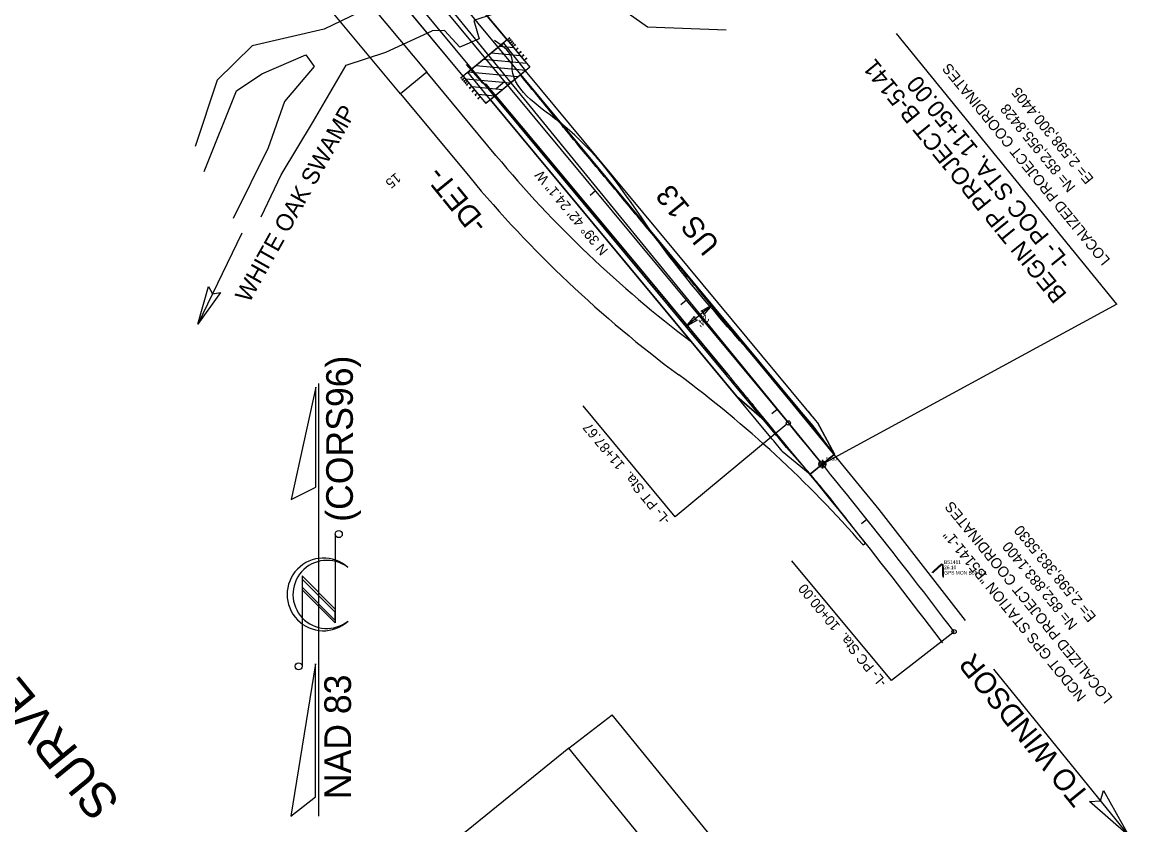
# Model space of a CAD drawing. Extents: x 2596159 to 2598075, y 851667 to 853493.
# Drawn here: x 2596820 to 2597521, y 852070 to 852579 of the extents above; entities that cross this region are included whole.
import ezdxf

# ---------------------------------------------------------------- set-up
doc = ezdxf.new("R2010")
doc.units = 0
for name, color, linetype in [('Cogo Default Point CELL', 7, 'Continuous'), ('CTL Sheet Text', 7, 'Continuous'), ('CTL Supplemental Horizontal and Vertical Cogo Comment', 7, 'Continuous'), ('CTL Supplemental Horizontal and Vertical Cogo Elevation', 7, 'Continuous'), ('CTL Supplemental Horizontal and Vertical Cogo Number', 7, 'Continuous'), ('Default', 7, 'Continuous'), ('Default Symbol CELL', 7, 'Continuous'), ('Default Symbol Cogo Number', 7, 'Continuous'), ('Exist Hydro Jurisdictional Stream or Body of Water', 7, 'Continuous'), ('Exist Roads EOP', 7, 'Continuous'), ('Old_Level_1', 7, 'Continuous'), ('Old_Level_2', 7, 'Continuous'), ('Old_Level_44', 7, 'Continuous'), ('Prop Dimension', 7, 'Continuous'), ('Prop Dimension Text', 7, 'Continuous'), ('Prop Horizontal Alignment', 7, 'Continuous'), ('Prop Horizontal Alignment Direction Label', 7, 'Continuous'), ('Prop Horizontal Alignment Station Label', 7, 'Continuous'), ('Prop Horizontal Alignment Tick Label', 7, 'Continuous'), ('Prop Horizontal Alignment Tick Large', 7, 'Continuous'), ('Prop Horizontal Alignment Tick Small', 7, 'Continuous'), ('Prop Shade Heavy', 7, 'Continuous'), ('Prop Shade Light', 7, 'Continuous'), ('Prop Shade Medium', 7, 'Continuous'), ('Prop Terminator CELL', 7, 'Continuous'), ('Sheet North Arrow CELL', 7, 'Continuous')]:
    doc.layers.add(name, color=color, linetype=linetype)

# ---------------------------------------------------------------- blocks, each defined once
blk = doc.blocks.new('DEFAULT SYMBOL')
at = {"layer": 'Default Symbol CELL'}
blk.add_lwpolyline([(0, 0.06), (0, -0.06), (0, 0), (0.06, 0), (-0.06, 0)], dxfattribs=at)
blk.add_circle((0, 0), 0.0469, dxfattribs=at)

msp = doc.modelspace()

# ---------------------------------------------------------------- linework, layer by layer
at = {"layer": 'Cogo Default Point CELL'}
msp.add_line((2597326.72, 852298.64), (2596871.93, 852856.6), dxfattribs=at)
at = {"layer": 'Default'}
for p, q in [((2597313.49, 852331.71), (2596966.4, 852749.69)), ((2597313.49, 852331.71), (2596966.4, 852749.69)), ((2597296.87, 852317.91), (2596949.78, 852735.9)), ((2597296.87, 852317.91), (2596949.78, 852735.9)), ((2597127.02, 852567.54), (2597075.27, 852629.86)), ((2597127.02, 852567.54), (2597075.27, 852629.86)), ((2597099.3, 852544.57), (2597047.55, 852606.88)), ((2597099.3, 852544.57), (2597047.55, 852606.88)), ((2597127.02, 852567.54), (2597099.3, 852544.57)), ((2597127.02, 852567.54), (2597099.3, 852544.57)), ((2597127.22, 852567.3), (2597126.77, 852567.34)), ((2597127.22, 852567.3), (2597126.77, 852567.34)), ((2597127.02, 852567.54), (2597128.4, 852568.69)), ((2597127.02, 852567.54), (2597137.79, 852554.55)), ((2597127.02, 852567.54), (2597141.38, 852550.22)), ((2597127.02, 852567.54), (2597141.38, 852550.22)), ((2597127.91, 852566.46), (2597129.3, 852567.61)), ((2597128.07, 852569.09), (2597128.73, 852568.29)), ((2597128.81, 852565.38), (2597130.2, 852566.53)), ((2597128.97, 852568.01), (2597129.63, 852567.21)), ((2597129.71, 852564.3), (2597131.09, 852565.44)), ((2597129.87, 852566.92), (2597130.53, 852566.13)), ((2597130.61, 852563.21), (2597131.99, 852564.36)), ((2597130.77, 852565.84), (2597131.42, 852565.05)), ((2597131.66, 852564.76), (2597132.32, 852563.96)), ((2597135.33, 852557.51), (2597116.97, 852559.21)), ((2597135.33, 852557.51), (2597116.97, 852559.21)), ((2597131.27, 852562.41), (2597121.87, 852563.28)), ((2597131.27, 852562.41), (2597121.87, 852563.28)), ((2597132.4, 852561.05), (2597133.79, 852562.2)), ((2597133.46, 852562.59), (2597134.12, 852561.8)), ((2597134.2, 852558.88), (2597135.58, 852560.03)), ((2597135.25, 852560.43), (2597135.91, 852559.63)), ((2597135.99, 852556.72), (2597137.38, 852557.87)), ((2597137.05, 852558.26), (2597137.71, 852557.47)), ((2597138.87, 852548.14), (2597107.16, 852551.08)), ((2597138.87, 852548.14), (2597107.16, 852551.08)), ((2597139.39, 852552.62), (2597112.07, 852555.15)), ((2597139.39, 852552.62), (2597112.07, 852555.15)), ((2597141.38, 852550.22), (2597113.66, 852527.24)), ((2597141.38, 852550.22), (2597113.66, 852527.24)), ((2597137.79, 852554.55), (2597139.17, 852555.7)), ((2597138.84, 852556.1), (2597139.5, 852555.3)), ((2597097.59, 852543.81), (2597098.25, 852543.02)), ((2597099.3, 852544.57), (2597097.92, 852543.42)), ((2597098.49, 852542.73), (2597099.14, 852541.94)), ((2597100.2, 852543.48), (2597098.81, 852542.33)), ((2597099.3, 852544.57), (2597110.07, 852531.57)), ((2597099.3, 852544.57), (2597113.66, 852527.24)), ((2597099.3, 852544.57), (2597113.66, 852527.24)), ((2597133.97, 852544.08), (2597102.26, 852547.02)), ((2597133.97, 852544.08), (2597102.26, 852547.02)), ((2597316.26, 852334.01), (2597138.62, 852547.94)), ((2597316.26, 852334.01), (2597138.62, 852547.94)), ((2597099.38, 852541.65), (2597100.04, 852540.85)), ((2597101.1, 852542.4), (2597099.71, 852541.25)), ((2597100.28, 852540.57), (2597100.94, 852539.77)), ((2597102, 852541.32), (2597100.61, 852540.17)), ((2597129.07, 852540.01), (2597100.91, 852542.62)), ((2597129.07, 852540.01), (2597100.91, 852542.62)), ((2597101.18, 852539.48), (2597101.84, 852538.69)), ((2597102.89, 852540.23), (2597101.51, 852539.09)), ((2597102.97, 852537.32), (2597103.63, 852536.52)), ((2597104.69, 852538.07), (2597103.3, 852536.92)), ((2597124.16, 852535.95), (2597104.97, 852537.73)), ((2597124.16, 852535.95), (2597104.97, 852537.73)), ((2597106.48, 852535.9), (2597105.1, 852534.76)), ((2597104.77, 852535.15), (2597105.43, 852534.36)), ((2597106.56, 852532.99), (2597107.22, 852532.19)), ((2597108.28, 852533.74), (2597106.89, 852532.59)), ((2597108.36, 852530.82), (2597109.02, 852530.03)), ((2597110.07, 852531.57), (2597108.69, 852530.43)), ((2597119.26, 852531.88), (2597109.03, 852532.83)), ((2597119.26, 852531.88), (2597109.03, 852532.83)), ((2597294.11, 852315.61), (2597116.45, 852529.55)), ((2597294.11, 852315.61), (2597116.45, 852529.55)), ((2597296.87, 852317.91), (2597119.22, 852531.85)), ((2597296.87, 852317.91), (2597119.22, 852531.85)), ((2597114.36, 852527.82), (2597113.09, 852527.94)), ((2597114.36, 852527.82), (2597113.09, 852527.94)), ((2596959.05, 852445.13), (2596931.26, 852387.33)), ((2597320.82, 852322.86), (2597313.49, 852331.71)), ((2597320.82, 852322.86), (2597313.49, 852331.71)), ((2597334.19, 852304.73), (2597320.82, 852322.86)), ((2597334.19, 852304.73), (2597320.82, 852322.86)), ((2597323.6, 852325.15), (2597334.4, 852304.89)), ((2597323.6, 852325.15), (2597334.4, 852304.89)), ((2597301.31, 852306.92), (2597318.95, 852292.3)), ((2597301.31, 852306.92), (2597318.95, 852292.3)), ((2597304.08, 852309.21), (2597318.95, 852292.3)), ((2597304.08, 852309.21), (2597318.95, 852292.3)), ((2597334.19, 852304.73), (2597318.95, 852292.3)), ((2597334.19, 852304.73), (2597318.95, 852292.3)), ((2597435.09, 852168.66), (2597520.84, 852063.15)), ((2597166.09, 852118.74), (2597193.67, 852139.85)), ((2597402.36, 851883.09), (2597193.67, 852139.85))]:
    msp.add_line(p, q, dxfattribs=at)
for radius, start in [(3768.44, 39.53171), (3768.44, 39.53171), (3739.64, 39.53368), (3739.64, 39.53368), (3743.24, 39.53368), (3743.24, 39.53368)]:
    msp.add_arc((2594417.1, 849926.51), radius, start, 39.70669, dxfattribs=at)
at = {"layer": 'Exist Hydro Jurisdictional Stream or Body of Water'}
for points in [[(2597265.86, 852573.79), (2597216.02, 852575.58), (2597188, 852595.69), (2597164.83, 852604.73), (2597144.53, 852592.43), (2597106.1, 852579.93), (2597109.29, 852568.3), (2597097.22, 852562.99), (2597087.33, 852573.49), (2597079.67, 852573.18)], [(2597055.58, 852595.78), (2597011.26, 852574.38), (2596965.55, 852563.75), (2596943.44, 852541.98), (2596929.45, 852499.99)], [(2597004.47, 852516.06), (2597025.06, 852551.55), (2597050.17, 852559.71), (2597079.67, 852573.18)], [(2596935.2, 852484.12), (2596955.7, 852535.15), (2596971.8, 852546), (2596999.59, 852558.14), (2597004.95, 852550.72), (2596986.01, 852528.39), (2596975.72, 852499.23), (2596953.54, 852454.4)], [(2596971.26, 852455.39), (2596983.92, 852482.08), (2597004.47, 852516.06)]]:
    msp.add_lwpolyline(points, dxfattribs=at)
at = {"layer": 'Exist Roads EOP'}
msp.add_line((2597402.92, 852185.41), (2597401.4, 852187.51), dxfattribs=at)
for points in [[(2597266.9, 852355.47), (2597207.25, 852427.27), (2597144.6, 852502.61), (2597114.01, 852539.24), (2597111.68, 852540.06), (2597101.35, 852551.99)], [(2597417.34, 852199.58), (2597362.64, 852269.95), (2597306.4, 852338.7), (2597282.34, 852368.01)]]:
    msp.add_lwpolyline(points, dxfattribs=at)
for points in [[(2597282.34, 852368.01), (2597222.69, 852439.98), (2597159.75, 852515.79), (2597130.28, 852551.69), (2597130.39, 852554.09), (2597119.16, 852567.08)], [(2597401.4, 852187.51), (2597346.84, 852257.76), (2597291.88, 852324.96), (2597266.9, 852355.47)]]:
    msp.add_spline(points, degree=3, dxfattribs=at)
at = {"layer": 'Old_Level_1'}
for p, q in [((2597166.09, 852118.74), (2596926.77, 851924.23)), ((2597375.45, 851861.15), (2597166.09, 852118.74)), ((2597145.99, 852101.95), (2597145.72, 852102.18))]:
    msp.add_line(p, q, dxfattribs=at)
at = {"layer": 'Prop Dimension'}
msp.add_line((2597257.02, 852399.71), (2597240.41, 852385.91), dxfattribs=at)
for points in [[(2597513.17, 852400.07), (2597373.7, 852571.68)], [(2597513.17, 852400.07), (2597326.72, 852298.64)]]:
    msp.add_lwpolyline(points, dxfattribs=at)
at = {"layer": 'Prop Horizontal Alignment'}
msp.add_line((2597305.18, 852324.81), (2596958.09, 852742.8), dxfattribs=at)
msp.add_arc((2594417.1, 849926.51), 3754.04, 37.12886, 39.70669, dxfattribs=at)
at = {"layer": 'Prop Horizontal Alignment Station Label'}
for p, q in [((2597233.58, 852265.35), (2597175.23, 852335.61)), ((2597304.14, 852323.95), (2597233.58, 852265.35)), ((2597370.48, 852161.53), (2597307.4, 852237.49)), ((2597410.13, 852192.49), (2597370.48, 852161.53))]:
    msp.add_line(p, q, dxfattribs=at)
for centre in [(2597305.18, 852324.81), (2597410.13, 852192.49)]:
    msp.add_circle(centre, 1.35, dxfattribs=at)
at = {"layer": 'Prop Horizontal Alignment Tick Large'}
msp.add_line((2597125.6, 852541.07), (2597120.06, 852536.47), dxfattribs=at)
at = {"layer": 'Prop Horizontal Alignment Tick Small'}
for p, q in [((2597183.1, 852471.83), (2597179.64, 852468.96)), ((2597240.6, 852402.59), (2597237.13, 852399.72)), ((2597298.09, 852333.35), (2597294.63, 852330.48)), ((2597354.95, 852263.59), (2597351.43, 852260.79))]:
    msp.add_line(p, q, dxfattribs=at)
at = {"layer": 'Prop Shade Heavy'}
for points in [[(2597099.3, 852544.57), (2597047.55, 852606.88), (2597075.27, 852629.86), (2597127.02, 852567.54)], [(2597076.15, 852547.09), (2597059.53, 852533.29), (2597007.78, 852595.61), (2597024.4, 852609.41)]]:
    msp.add_lwpolyline(points, close=True, dxfattribs=at)
at = {"layer": 'Prop Shade Light'}
for p, q in [((2597138.62, 852547.94), (2597135.46, 852545.32)), ((2597316.26, 852334.01), (2597138.62, 852547.94)), ((2597116.45, 852529.55), (2597272.64, 852341.46)), ((2597207.25, 852427.27), (2597266.9, 852355.47)), ((2597320.82, 852322.86), (2597282.34, 852368.01)), ((2597282.34, 852368.01), (2597305.64, 852339.62)), ((2597272.64, 852341.46), (2597289.78, 852326.45)), ((2597323.6, 852325.15), (2597316.26, 852334.01)), ((2597289.78, 852326.45), (2597290.31, 852326.89))]:
    msp.add_line(p, q, dxfattribs=at)
msp.add_lwpolyline([(2597116.45, 852529.55), (2597102.22, 852547.05), (2597121.49, 852562.95), (2597124.76, 852565.52), (2597138.62, 852547.94)], close=True, dxfattribs=at)
for points in [[(2597135.46, 852545.32), (2597133.97, 852544.08), (2597129.07, 852540.01), (2597124.16, 852535.95), (2597119.79, 852532.32)], [(2597119.79, 852532.32), (2597119.26, 852531.88), (2597116.45, 852529.55)], [(2597266.9, 852355.47), (2597207.25, 852427.27), (2597144.6, 852502.61), (2597119.79, 852532.32)], [(2597119.79, 852532.32), (2597144.6, 852502.61), (2597207.25, 852427.27)], [(2597305.64, 852339.62), (2597334.4, 852304.89), (2597323.6, 852325.15)], [(2597304.08, 852309.21), (2597318.95, 852292.3), (2597334.19, 852304.73), (2597320.82, 852322.86)]]:
    msp.add_lwpolyline(points, dxfattribs=at)
for points, degree in [([(2597282.34, 852368.01), (2597262.45, 852392), (2597242.57, 852415.99), (2597222.69, 852439.98), (2597201.73, 852465.27), (2597180.73, 852490.52), (2597159.75, 852515.79), (2597151.61, 852525.59), (2597143.51, 852535.44), (2597135.46, 852545.32)], 3), ([(2597135.46, 852545.32), (2597143.51, 852535.44), (2597151.61, 852525.59), (2597159.75, 852515.79), (2597180.73, 852490.52), (2597201.73, 852465.27), (2597222.69, 852439.98)], 3), ([(2597222.69, 852439.98), (2597242.57, 852415.99), (2597262.45, 852392), (2597282.34, 852368.01)], 2), ([(2597290.31, 852326.89), (2597282.5, 852336.41), (2597274.7, 852345.94), (2597266.9, 852355.47)], 2), ([(2597266.9, 852355.47), (2597274.7, 852345.94), (2597282.5, 852336.41), (2597304.08, 852309.21)], 2)]:
    msp.add_open_spline(points, degree=degree, dxfattribs=at)
at = {"layer": 'Prop Shade Medium'}
for p, q in [((2597076.15, 852547.09), (2597059.53, 852533.29)), ((2597119.99, 852494.3), (2597076.15, 852547.09)), ((2597059.53, 852533.29), (2597103.37, 852480.5)), ((2597272.64, 852341.46), (2597243.77, 852376.23)), ((2597289.78, 852326.45), (2597272.64, 852341.46)), ((2597290.31, 852326.89), (2597289.78, 852326.45)), ((2597352.58, 852247.44), (2597353.98, 852248.57))]:
    msp.add_line(p, q, dxfattribs=at)
for centre, radius, start, end in [((2597688.44, 852966.35), 738.9, 219.70669, 233.00058), ((2597688.44, 852966.35), 760.5, 219.70669, 233.47068), ((2596795.95, 851761.5), 738.9, 41.12046, 53.47068)]:
    msp.add_arc(centre, radius, start, end, dxfattribs=at)
msp.add_open_spline([(2597353.98, 852248.57), (2597351.6, 852251.63), (2597349.22, 852254.69), (2597346.84, 852257.76), (2597329.09, 852280.61), (2597310.22, 852302.57), (2597291.88, 852324.96), (2597291.36, 852325.6), (2597290.83, 852326.25), (2597290.31, 852326.89)], degree=3, dxfattribs=at)
at = {"layer": 'Prop Terminator CELL'}
for points in [[(2596945.56, 852407.42), (2596931.26, 852387.33), (2596937.95, 852411.23), (2596940.5, 852406.56)], [(2597249.9, 852395.61), (2597257.02, 852399.71), (2597251.68, 852393.4), (2597251.55, 852395.17)], [(2597247.53, 852390.01), (2597240.4, 852385.91), (2597245.75, 852392.22), (2597245.87, 852390.46)], [(2597504.74, 852091.82), (2597520.84, 852063.15), (2597495.82, 852084.8), (2597502.9, 852085.22)]]:
    msp.add_lwpolyline(points, close=True, dxfattribs=at)
at = {"layer": 'Sheet North Arrow CELL'}
for p, q in [((2597007.88, 852075.57), (2597007.88, 852349.78)), ((2597018.22, 852254.36), (2597018.22, 852198.08)), ((2597018.22, 852206.85), (2596997.25, 852227.82)), ((2596997.25, 852227.82), (2596997.25, 852170.61)), ((2597025.98, 852233.39), (2597026.28, 852233.18)), ((2597018.22, 852204.79), (2596997.25, 852225.75)), ((2596997.25, 852225.75), (2596997.25, 852220.61)), ((2597018.22, 852199.64), (2596997.25, 852220.61)), ((2596997.25, 852220.61), (2597018.22, 852199.64)), ((2597018.22, 852198.08), (2596997.25, 852219.05)), ((2597018.22, 852199.64), (2597018.22, 852204.79))]:
    msp.add_line(p, q, dxfattribs=at)
for points in [[(2597005.98, 852347.38), (2596990.33, 852276.17), (2597005.98, 852284.1)], [(2597005.65, 852172.18), (2596990.12, 852075.57), (2597005.65, 852087.8)]]:
    msp.add_lwpolyline(points, close=True, dxfattribs=at)
for centre in [(2597020.45, 852254.31), (2596995.02, 852170.53)]:
    msp.add_circle(centre, 2.24, dxfattribs=at)
for centre, radius, start, end in [((2597010.8, 852216.11), 23.03, 47.84002, 312.39406), ((2597013.02, 852216.11), 21.59, 53.09504, 308.62871)]:
    msp.add_arc(centre, radius, start, end, dxfattribs=at)

# ---------------------------------------------------------------- block references
at = {"layer": 'Default Symbol CELL', "xscale": 44.99999999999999, "yscale": 45.00000000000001}
msp.add_blockref('DEFAULT SYMBOL', (2597326.72, 852298.64), dxfattribs=at)

# ---------------------------------------------------------------- texts
at = {"layer": 'CTL Sheet Text'}
for s, p in [('LOCALIZED PROJECT COORDINATES', (2597509.36, 852428.13)), ('E= 2,598,300.4405', (2597498.96, 852479.64)), ('N= 852,955.8428', (2597487.41, 852474.44)), ('LOCALIZED PROJECT COORDINATES', (2597510.94, 852150.44)), ('E= 2,598,383.5830', (2597500.48, 852202.01)), ('NCDOT GPS STATION "B5141-1"', (2597494.19, 852151.61)), ('N= 852,883.1400', (2597488.72, 852197.07))]:
    msp.add_text(s, height=6.6699, rotation=129.18354, dxfattribs=at).set_placement(p)
at = {"layer": 'CTL Supplemental Horizontal and Vertical Cogo Comment'}
msp.add_text('GPS MON B5141-1', height=2.25, rotation=360, dxfattribs=at).set_placement((2597403.8, 852228.7))
at = {"layer": 'CTL Supplemental Horizontal and Vertical Cogo Elevation'}
msp.add_text('26.10', height=2.25, rotation=360, dxfattribs=at).set_placement((2597403.8, 852232.08))
at = {"layer": 'CTL Supplemental Horizontal and Vertical Cogo Number'}
msp.add_text('B51411', height=2.25, rotation=360, dxfattribs=at).set_placement((2597403.8, 852235.45))
at = {"layer": 'Default'}
for s, height, rotation, p in [('WHITE OAK SWAMP', 10.8, 60.80817, (2596963.73, 852400.32)), ('-DET-', 13.5, 129.10281, (2597115.53, 852451.18)), ('US 13', 13.5, 129.10281, (2597262.38, 852438.06)), ('TO WINDSOR', 13.5, 129.10281, (2597496.63, 852088.87))]:
    msp.add_text(s, height=height, rotation=rotation, dxfattribs=at).set_placement(p)
at = {"layer": 'Default Symbol Cogo Number'}
msp.add_text('5000', height=2.25, rotation=360, dxfattribs=at).set_placement((2597328.97, 852300.89))
at = {"layer": 'Old_Level_2'}
msp.add_text('>', height=12, rotation=66.97335, dxfattribs=at).set_placement((2597404.73, 852225.34))
at = {"layer": 'Old_Level_44'}
msp.add_text('SURVEY CONTROL SHEET B-5141', height=22.5002, rotation=129.18346, dxfattribs=at).set_placement((2596882.78, 852084.96))
at = {"layer": 'Prop Dimension Text'}
for s, height, rotation, p in [('BEGIN TIP PROJECT B-5141', 10.8, 129.10268, (2597482.02, 852406.32)), ('-L- POC STA. 11+50.00', 10.8, 129.10268, (2597484.56, 852426.64)), ("24'", 4.5, 219.70669, (2597252.82, 852393.68))]:
    msp.add_text(s, height=height, rotation=rotation, dxfattribs=at).set_placement(p)
at = {"layer": 'Prop Horizontal Alignment Direction Label'}
msp.add_text('N 39%%d 42\' 24.1" W', height=6.3, rotation=129.70669, dxfattribs=at).set_placement((2597191.43, 852434.28))
at = {"layer": 'Prop Horizontal Alignment Station Label'}
for s, rotation, p in [('-L- PT Sta.  11+87.67', 129.70669, (2597230.97, 852263.43)), ('-L- PC Sta.  10+00.00', 129.66534, (2597367.95, 852160.57))]:
    msp.add_text(s, height=6.3, rotation=rotation, dxfattribs=at).set_placement(p)
at = {"layer": 'Prop Horizontal Alignment Tick Label'}
msp.add_text('15', height=6.3, rotation=219.70669, dxfattribs=at).set_placement((2597056.65, 852483.72))
at = {"layer": 'Sheet North Arrow CELL'}
for s, p in [('(CORS96)', (2597029.37, 852262.12)), ('NAD 83', (2597028.19, 852086.31))]:
    msp.add_text(s, height=16.875, rotation=90, dxfattribs=at).set_placement(p)

doc.saveas('drawing.dxf')
